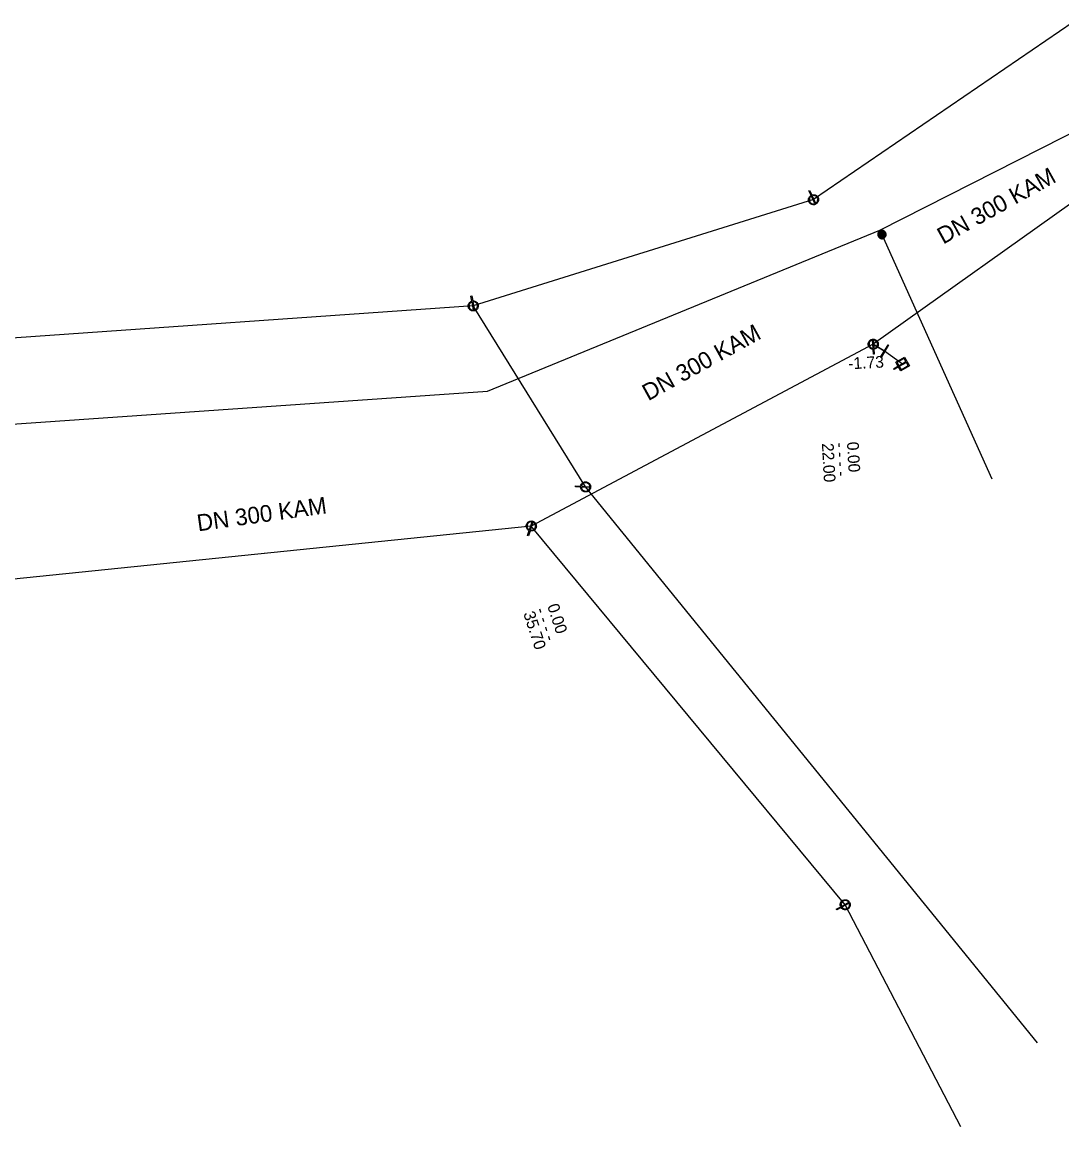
# Model space of a CAD drawing. Extents: x -818321 to -817653, y -1049725 to -1049329.
# Drawn here: x -817861 to -817798.9, y -1049449.2 to -1049383.2 of the extents above; entities that cross this region are included whole.
import ezdxf

# ---------------------------------------------------------------- set-up
doc = ezdxf.new("R2010")
doc.units = 0
doc.layers.add('Default', color=7, linetype='Continuous')
doc.layers.add('Level 0', color=7, linetype='Continuous')

msp = doc.modelspace()

# ---------------------------------------------------------------- linework, layer by layer
at = {"layer": 'Default'}
for points in [[(-817813.843, -1049393.529), (-817813.97, -1049393.256), (-817813.925, -1049393.236), (-817813.798, -1049393.508)], [(-817813.611, -1049394.026), (-817813.821, -1049393.575)], [(-817813.776, -1049393.554), (-817813.566, -1049394.005)], [(-817834.098, -1049399.844), (-817834.156, -1049399.549), (-817834.107, -1049399.539), (-817834.05, -1049399.835)], [(-817833.994, -1049400.382), (-817834.089, -1049399.894)], [(-817834.04, -1049399.885), (-817833.945, -1049400.373)], [(-817810.137, -1049402.668), (-817810.163, -1049402.171)], [(-817810.126, -1049402.428), (-817810.108, -1049402.418), (-817809.45, -1049402.813), (-817809.233, -1049402.449), (-817809.207, -1049402.465), (-817809.659, -1049403.218), (-817809.685, -1049403.202), (-817809.466, -1049402.838), (-817810.114, -1049402.45), (-817810.126, -1049402.428)], [(-817810.114, -1049402.169), (-817810.088, -1049402.666)], [(-817810.085, -1049402.717), (-817810.069, -1049403.017), (-817810.118, -1049403.019), (-817810.134, -1049402.719)], [(-817808.624, -1049403.778), (-817808.884, -1049403.928), (-817808.908, -1049403.885), (-817808.649, -1049403.735), (-817808.786, -1049403.497), (-817808.267, -1049403.197), (-817807.967, -1049403.717), (-817808.486, -1049404.017), (-817808.624, -1049403.778)], [(-817808.606, -1049403.711), (-817808.172, -1049403.46), (-817808.285, -1049403.264), (-817808.719, -1049403.515), (-817808.606, -1049403.711)], [(-817808.581, -1049403.753), (-817808.468, -1049403.949), (-817808.034, -1049403.699), (-817808.147, -1049403.503), (-817808.581, -1049403.753)], [(-817827.605, -1049410.949), (-817827.905, -1049410.933), (-817827.903, -1049410.884), (-817827.603, -1049410.9)], [(-817827.057, -1049410.978), (-817827.554, -1049410.952)], [(-817827.552, -1049410.903), (-817827.055, -1049410.929)], [(-817830.655, -1049413.504), (-817830.493, -1049413.034)], [(-817830.447, -1049413.05), (-817830.609, -1049413.52)], [(-817830.626, -1049413.568), (-817830.723, -1049413.852), (-817830.77, -1049413.836), (-817830.672, -1049413.552)], [(-817812.048, -1049436.055), (-817812.311, -1049436.201), (-817812.335, -1049436.158), (-817812.072, -1049436.012)], [(-817812.028, -1049435.987), (-817811.593, -1049435.746)], [(-817811.569, -1049435.789), (-817812.004, -1049436.03)]]:
    msp.add_lwpolyline(points, dxfattribs=at)
for points in [[(-817813.798, -1049393.508), (-817813.74, -1049393.485), (-817813.668, -1049393.491), (-817813.587, -1049393.496), (-817813.521, -1049393.544), (-817813.455, -1049393.592), (-817813.422, -1049393.663), (-817813.389, -1049393.734), (-817813.395, -1049393.817), (-817813.401, -1049393.899), (-817813.45, -1049393.964), (-817813.498, -1049394.029), (-817813.567, -1049394.062), (-817813.636, -1049394.094), (-817813.717, -1049394.089), (-817813.798, -1049394.084), (-817813.865, -1049394.036), (-817813.933, -1049393.988), (-817813.966, -1049393.917), (-817813.999, -1049393.846), (-817813.993, -1049393.764), (-817813.987, -1049393.683), (-817813.939, -1049393.617), (-817813.897, -1049393.559), (-817813.843, -1049393.529)], [(-817813.821, -1049393.575), (-817813.864, -1049393.599), (-817813.899, -1049393.647), (-817813.939, -1049393.702), (-817813.943, -1049393.769), (-817813.948, -1049393.837), (-817813.921, -1049393.895), (-817813.893, -1049393.954), (-817813.837, -1049393.995), (-817813.781, -1049394.035), (-817813.713, -1049394.039), (-817813.656, -1049394.042), (-817813.611, -1049394.026)], [(-817813.566, -1049394.005), (-817813.525, -1049393.981), (-817813.49, -1049393.934), (-817813.449, -1049393.88), (-817813.444, -1049393.811), (-817813.44, -1049393.743), (-817813.467, -1049393.684), (-817813.495, -1049393.625), (-817813.549, -1049393.585), (-817813.604, -1049393.546), (-817813.672, -1049393.541), (-817813.73, -1049393.537), (-817813.776, -1049393.554)], [(-817809.837, -1049395.972), (-817809.863, -1049395.914), (-817809.857, -1049395.846), (-817809.852, -1049395.779), (-817809.811, -1049395.723), (-817809.77, -1049395.668), (-817809.71, -1049395.641), (-817809.651, -1049395.615), (-817809.583, -1049395.621), (-817809.515, -1049395.627), (-817809.461, -1049395.668), (-817809.407, -1049395.709), (-817809.38, -1049395.768), (-817809.354, -1049395.827), (-817809.36, -1049395.895), (-817809.366, -1049395.963), (-817809.407, -1049396.017), (-817809.447, -1049396.072), (-817809.507, -1049396.098), (-817809.567, -1049396.125), (-817809.635, -1049396.119), (-817809.704, -1049396.112), (-817809.758, -1049396.071), (-817809.811, -1049396.03), (-817809.837, -1049395.972)], [(-817809.816, -1049395.962), (-817809.792, -1049396.014), (-817809.744, -1049396.052), (-817809.695, -1049396.09), (-817809.633, -1049396.095), (-817809.571, -1049396.101), (-817809.516, -1049396.077), (-817809.463, -1049396.053), (-817809.425, -1049396.004), (-817809.388, -1049395.955), (-817809.383, -1049395.893), (-817809.378, -1049395.831), (-817809.402, -1049395.778), (-817809.426, -1049395.724), (-817809.475, -1049395.687), (-817809.524, -1049395.649), (-817809.586, -1049395.644), (-817809.647, -1049395.639), (-817809.701, -1049395.663), (-817809.755, -1049395.687), (-817809.792, -1049395.737), (-817809.829, -1049395.788), (-817809.834, -1049395.849), (-817809.839, -1049395.91), (-817809.816, -1049395.962)], [(-817809.8, -1049395.955), (-817809.821, -1049395.907), (-817809.817, -1049395.85), (-817809.813, -1049395.794), (-817809.778, -1049395.747), (-817809.744, -1049395.701), (-817809.694, -1049395.678), (-817809.644, -1049395.656), (-817809.587, -1049395.661), (-817809.531, -1049395.666), (-817809.485, -1049395.7), (-817809.439, -1049395.735), (-817809.417, -1049395.785), (-817809.395, -1049395.834), (-817809.4, -1049395.891), (-817809.405, -1049395.948), (-817809.439, -1049395.994), (-817809.474, -1049396.039), (-817809.523, -1049396.061), (-817809.573, -1049396.083), (-817809.631, -1049396.078), (-817809.688, -1049396.073), (-817809.733, -1049396.038), (-817809.778, -1049396.003), (-817809.8, -1049395.955)], [(-817809.78, -1049395.947), (-817809.748, -1049396.018), (-817809.676, -1049396.045), (-817809.603, -1049396.073), (-817809.532, -1049396.041), (-817809.461, -1049396.009), (-817809.434, -1049395.937), (-817809.406, -1049395.865), (-817809.437, -1049395.794), (-817809.469, -1049395.723), (-817809.541, -1049395.695), (-817809.614, -1049395.667), (-817809.685, -1049395.698), (-817809.756, -1049395.73), (-817809.784, -1049395.802), (-817809.812, -1049395.875), (-817809.78, -1049395.947)], [(-817809.759, -1049395.937), (-817809.787, -1049395.875), (-817809.762, -1049395.811), (-817809.738, -1049395.748), (-817809.676, -1049395.721), (-817809.613, -1049395.693), (-817809.55, -1049395.717), (-817809.487, -1049395.742), (-817809.459, -1049395.804), (-817809.431, -1049395.866), (-817809.456, -1049395.929), (-817809.48, -1049395.993), (-817809.542, -1049396.02), (-817809.604, -1049396.048), (-817809.668, -1049396.024), (-817809.731, -1049396), (-817809.759, -1049395.937)], [(-817809.741, -1049395.929), (-817809.716, -1049395.984), (-817809.661, -1049396.005), (-817809.605, -1049396.027), (-817809.55, -1049396.002), (-817809.496, -1049395.978), (-817809.474, -1049395.922), (-817809.453, -1049395.867), (-817809.477, -1049395.812), (-817809.501, -1049395.757), (-817809.557, -1049395.736), (-817809.613, -1049395.714), (-817809.668, -1049395.739), (-817809.722, -1049395.763), (-817809.744, -1049395.819), (-817809.765, -1049395.874), (-817809.741, -1049395.929)], [(-817809.723, -1049395.921), (-817809.744, -1049395.873), (-817809.725, -1049395.825), (-817809.707, -1049395.777), (-817809.659, -1049395.756), (-817809.612, -1049395.735), (-817809.564, -1049395.753), (-817809.516, -1049395.772), (-817809.494, -1049395.819), (-817809.473, -1049395.866), (-817809.492, -1049395.915), (-817809.51, -1049395.963), (-817809.558, -1049395.984), (-817809.605, -1049396.005), (-817809.653, -1049395.987), (-817809.702, -1049395.969), (-817809.723, -1049395.921)], [(-817809.702, -1049395.911), (-817809.684, -1049395.95), (-817809.645, -1049395.965), (-817809.606, -1049395.98), (-817809.567, -1049395.963), (-817809.529, -1049395.946), (-817809.514, -1049395.907), (-817809.499, -1049395.867), (-817809.516, -1049395.829), (-817809.533, -1049395.791), (-817809.572, -1049395.775), (-817809.612, -1049395.76), (-817809.65, -1049395.777), (-817809.689, -1049395.795), (-817809.704, -1049395.834), (-817809.719, -1049395.873), (-817809.702, -1049395.911)], [(-817809.686, -1049395.904), (-817809.7, -1049395.872), (-817809.688, -1049395.84), (-817809.675, -1049395.808), (-817809.643, -1049395.793), (-817809.611, -1049395.779), (-817809.578, -1049395.791), (-817809.546, -1049395.804), (-817809.532, -1049395.836), (-817809.518, -1049395.868), (-817809.53, -1049395.9), (-817809.542, -1049395.933), (-817809.575, -1049395.947), (-817809.607, -1049395.961), (-817809.639, -1049395.949), (-817809.671, -1049395.937), (-817809.686, -1049395.904)], [(-817809.666, -1049395.895), (-817809.655, -1049395.919), (-817809.631, -1049395.928), (-817809.607, -1049395.937), (-817809.583, -1049395.927), (-817809.56, -1049395.916), (-817809.55, -1049395.892), (-817809.541, -1049395.868), (-817809.551, -1049395.845), (-817809.562, -1049395.821), (-817809.586, -1049395.812), (-817809.61, -1049395.802), (-817809.634, -1049395.813), (-817809.658, -1049395.823), (-817809.667, -1049395.847), (-817809.676, -1049395.871), (-817809.666, -1049395.895)], [(-817809.644, -1049395.886), (-817809.651, -1049395.871), (-817809.645, -1049395.856), (-817809.64, -1049395.841), (-817809.624, -1049395.834), (-817809.61, -1049395.828), (-817809.595, -1049395.833), (-817809.58, -1049395.839), (-817809.573, -1049395.854), (-817809.566, -1049395.869), (-817809.572, -1049395.884), (-817809.578, -1049395.899), (-817809.593, -1049395.906), (-817809.608, -1049395.913), (-817809.623, -1049395.907), (-817809.638, -1049395.901), (-817809.644, -1049395.886)], [(-817809.63, -1049395.88), (-817809.626, -1049395.889), (-817809.617, -1049395.892), (-817809.608, -1049395.896), (-817809.599, -1049395.891), (-817809.59, -1049395.888), (-817809.587, -1049395.878), (-817809.583, -1049395.869), (-817809.587, -1049395.861), (-817809.591, -1049395.851), (-817809.6, -1049395.848), (-817809.609, -1049395.845), (-817809.618, -1049395.849), (-817809.627, -1049395.853), (-817809.631, -1049395.862), (-817809.634, -1049395.87), (-817809.63, -1049395.88)], [(-817834.05, -1049399.835), (-817833.988, -1049399.827), (-817833.92, -1049399.849), (-817833.842, -1049399.874), (-817833.79, -1049399.937), (-817833.737, -1049399.999), (-817833.723, -1049400.076), (-817833.708, -1049400.153), (-817833.733, -1049400.231), (-817833.759, -1049400.31), (-817833.822, -1049400.361), (-817833.885, -1049400.413), (-817833.96, -1049400.428), (-817834.034, -1049400.442), (-817834.112, -1049400.418), (-817834.19, -1049400.394), (-817834.243, -1049400.33), (-817834.297, -1049400.267), (-817834.311, -1049400.19), (-817834.326, -1049400.114), (-817834.301, -1049400.036), (-817834.276, -1049399.958), (-817834.213, -1049399.906), (-817834.158, -1049399.86), (-817834.098, -1049399.844)], [(-817834.089, -1049399.894), (-817834.136, -1049399.907), (-817834.181, -1049399.945), (-817834.233, -1049399.988), (-817834.254, -1049400.053), (-817834.275, -1049400.117), (-817834.263, -1049400.181), (-817834.25, -1049400.245), (-817834.206, -1049400.297), (-817834.161, -1049400.35), (-817834.096, -1049400.37), (-817834.041, -1049400.387), (-817833.994, -1049400.382)], [(-817833.945, -1049400.373), (-817833.9, -1049400.36), (-817833.854, -1049400.323), (-817833.802, -1049400.28), (-817833.78, -1049400.215), (-817833.759, -1049400.149), (-817833.771, -1049400.085), (-817833.784, -1049400.022), (-817833.827, -1049399.97), (-817833.871, -1049399.918), (-817833.936, -1049399.897), (-817833.991, -1049399.879), (-817834.04, -1049399.885)], [(-817810.134, -1049402.719), (-817810.196, -1049402.718), (-817810.261, -1049402.686), (-817810.334, -1049402.651), (-817810.378, -1049402.582), (-817810.421, -1049402.512), (-817810.425, -1049402.434), (-817810.429, -1049402.356), (-817810.392, -1049402.282), (-817810.356, -1049402.208), (-817810.286, -1049402.166), (-817810.217, -1049402.123), (-817810.141, -1049402.119), (-817810.065, -1049402.115), (-817809.992, -1049402.15), (-817809.918, -1049402.185), (-817809.874, -1049402.255), (-817809.83, -1049402.325), (-817809.826, -1049402.403), (-817809.822, -1049402.481), (-817809.857, -1049402.554), (-817809.893, -1049402.628), (-817809.962, -1049402.671), (-817810.023, -1049402.709), (-817810.085, -1049402.717)], [(-817810.163, -1049402.171), (-817810.21, -1049402.178), (-817810.26, -1049402.208), (-817810.318, -1049402.243), (-817810.348, -1049402.305), (-817810.379, -1049402.367), (-817810.375, -1049402.432), (-817810.372, -1049402.497), (-817810.336, -1049402.554), (-817810.3, -1049402.612), (-817810.239, -1049402.641), (-817810.186, -1049402.667), (-817810.137, -1049402.668)], [(-817810.088, -1049402.666), (-817810.039, -1049402.66), (-817809.989, -1049402.628), (-817809.931, -1049402.592), (-817809.902, -1049402.531), (-817809.872, -1049402.471), (-817809.875, -1049402.406), (-817809.879, -1049402.341), (-817809.916, -1049402.283), (-817809.952, -1049402.224), (-817810.014, -1049402.195), (-817810.066, -1049402.17), (-817810.114, -1049402.169)], [(-817827.603, -1049410.9), (-817827.595, -1049410.838), (-817827.557, -1049410.777), (-817827.514, -1049410.708), (-817827.44, -1049410.672), (-817827.367, -1049410.637), (-817827.289, -1049410.641), (-817827.211, -1049410.645), (-817827.141, -1049410.689), (-817827.071, -1049410.733), (-817827.036, -1049410.806), (-817827.001, -1049410.88), (-817827.005, -1049410.956), (-817827.009, -1049411.031), (-817827.052, -1049411.101), (-817827.094, -1049411.171), (-817827.168, -1049411.207), (-817827.242, -1049411.244), (-817827.32, -1049411.24), (-817827.398, -1049411.236), (-817827.468, -1049411.193), (-817827.537, -1049411.149), (-817827.572, -1049411.076), (-817827.604, -1049411.011), (-817827.605, -1049410.949)], [(-817827.554, -1049410.952), (-817827.553, -1049411.001), (-817827.527, -1049411.054), (-817827.498, -1049411.115), (-817827.44, -1049411.151), (-817827.383, -1049411.187), (-817827.318, -1049411.19), (-817827.253, -1049411.194), (-817827.191, -1049411.163), (-817827.129, -1049411.133), (-817827.094, -1049411.075), (-817827.064, -1049411.025), (-817827.057, -1049410.978)], [(-817827.055, -1049410.929), (-817827.056, -1049410.881), (-817827.081, -1049410.828), (-817827.11, -1049410.767), (-817827.169, -1049410.73), (-817827.227, -1049410.694), (-817827.292, -1049410.69), (-817827.357, -1049410.687), (-817827.417, -1049410.717), (-817827.478, -1049410.746), (-817827.514, -1049410.804), (-817827.546, -1049410.854), (-817827.552, -1049410.903)], [(-817830.672, -1049413.552), (-817830.729, -1049413.528), (-817830.777, -1049413.474), (-817830.832, -1049413.414), (-817830.846, -1049413.334), (-817830.86, -1049413.253), (-817830.835, -1049413.179), (-817830.809, -1049413.105), (-817830.748, -1049413.05), (-817830.686, -1049412.995), (-817830.606, -1049412.982), (-817830.526, -1049412.969), (-817830.454, -1049412.993), (-817830.382, -1049413.018), (-817830.327, -1049413.078), (-817830.272, -1049413.138), (-817830.257, -1049413.219), (-817830.242, -1049413.3), (-817830.268, -1049413.375), (-817830.293, -1049413.448), (-817830.354, -1049413.503), (-817830.414, -1049413.558), (-817830.495, -1049413.572), (-817830.565, -1049413.585), (-817830.626, -1049413.568)], [(-817830.493, -1049413.034), (-817830.54, -1049413.022), (-817830.597, -1049413.031), (-817830.664, -1049413.042), (-817830.716, -1049413.088), (-817830.767, -1049413.134), (-817830.788, -1049413.196), (-817830.809, -1049413.257), (-817830.797, -1049413.324), (-817830.786, -1049413.39), (-817830.74, -1049413.441), (-817830.701, -1049413.485), (-817830.655, -1049413.504)], [(-817830.609, -1049413.52), (-817830.561, -1049413.533), (-817830.503, -1049413.522), (-817830.436, -1049413.511), (-817830.386, -1049413.465), (-817830.336, -1049413.42), (-817830.315, -1049413.359), (-817830.294, -1049413.297), (-817830.306, -1049413.229), (-817830.318, -1049413.162), (-817830.364, -1049413.112), (-817830.403, -1049413.069), (-817830.447, -1049413.05)], [(-817812.072, -1049436.012), (-817812.099, -1049435.956), (-817812.098, -1049435.884), (-817812.099, -1049435.802), (-817812.055, -1049435.733), (-817812.012, -1049435.664), (-817811.944, -1049435.626), (-817811.875, -1049435.588), (-817811.793, -1049435.588), (-817811.71, -1049435.589), (-817811.641, -1049435.633), (-817811.573, -1049435.676), (-817811.536, -1049435.743), (-817811.499, -1049435.809), (-817811.498, -1049435.891), (-817811.497, -1049435.972), (-817811.541, -1049436.042), (-817811.584, -1049436.113), (-817811.653, -1049436.151), (-817811.721, -1049436.189), (-817811.803, -1049436.189), (-817811.885, -1049436.189), (-817811.954, -1049436.145), (-817812.015, -1049436.107), (-817812.048, -1049436.055)], [(-817811.593, -1049435.746), (-817811.619, -1049435.707), (-817811.668, -1049435.675), (-817811.725, -1049435.638), (-817811.794, -1049435.638), (-817811.863, -1049435.638), (-817811.92, -1049435.67), (-817811.977, -1049435.701), (-817812.012, -1049435.759), (-817812.048, -1049435.816), (-817812.048, -1049435.884), (-817812.048, -1049435.943), (-817812.028, -1049435.987)], [(-817812.004, -1049436.03), (-817811.977, -1049436.072), (-817811.927, -1049436.103), (-817811.869, -1049436.139), (-817811.802, -1049436.139), (-817811.734, -1049436.139), (-817811.677, -1049436.107), (-817811.62, -1049436.076), (-817811.584, -1049436.017), (-817811.548, -1049435.959), (-817811.549, -1049435.891), (-817811.549, -1049435.833), (-817811.569, -1049435.789)]]:
    msp.add_open_spline(points, degree=3, dxfattribs=at)
at = {"layer": 'Level 0'}
for p, q in [((-817798.195, -1049383.185), (-817813.696, -1049393.785)), ((-817809.729, -1049395.603), (-817795.289, -1049388.269)), ((-817795.085, -1049391.702), (-817810.125, -1049402.424)), ((-817813.696, -1049393.785), (-817834.018, -1049400.128)), ((-817833.169, -1049405.216), (-817809.729, -1049395.603)), ((-817809.729, -1049395.603), (-817809.609, -1049395.869)), ((-817809.609, -1049395.869), (-817809.608, -1049395.87)), ((-817809.608, -1049395.87), (-817803.038, -1049410.45)), ((-817834.018, -1049400.128), (-817870.011, -1049402.66)), ((-817827.31, -1049410.94), (-817834.018, -1049400.128)), ((-817810.125, -1049402.424), (-817830.553, -1049413.282)), ((-817809.45, -1049402.828), (-817810.125, -1049402.424)), ((-817808.384, -1049403.614), (-817809.45, -1049402.828)), ((-817895.341, -1049409.545), (-817833.169, -1049405.216)), ((-817800.324, -1049444.134), (-817827.31, -1049410.94)), ((-817830.553, -1049413.282), (-817864.695, -1049416.789)), ((-817811.803, -1049435.891), (-817830.553, -1049413.282)), ((-817804.888, -1049449.156), (-817811.803, -1049435.891))]:
    msp.add_line(p, q, dxfattribs=at)

# ---------------------------------------------------------------- texts
for s, height, rotation, p in [('DN 300 KAM', 1, 29, (-817805.949, -1049396.474)), ('DN 300 KAM', 1, 29, (-817823.566, -1049405.827)), ('-1.73', 0.7, 3, (-817811.604, -1049403.921)), ('22.00', 0.7, 273, (-817813.194, -1049408.341)), ('- - - -', 0.7, 273, (-817812.445, -1049408.302)), ('0.00', 0.7, 273, (-817811.696, -1049408.263)), ('DN 300 KAM', 1, 8, (-817850.446, -1049413.598)), ('35.70', 0.7, 288, (-817831.035, -1049418.496)), ('- - - -', 0.7, 288, (-817830.32, -1049418.27)), ('0.00', 0.7, 288, (-817829.605, -1049418.043))]:
    msp.add_text(s, height=height, rotation=rotation, dxfattribs=at).set_placement(p)

doc.saveas('drawing.dxf')
